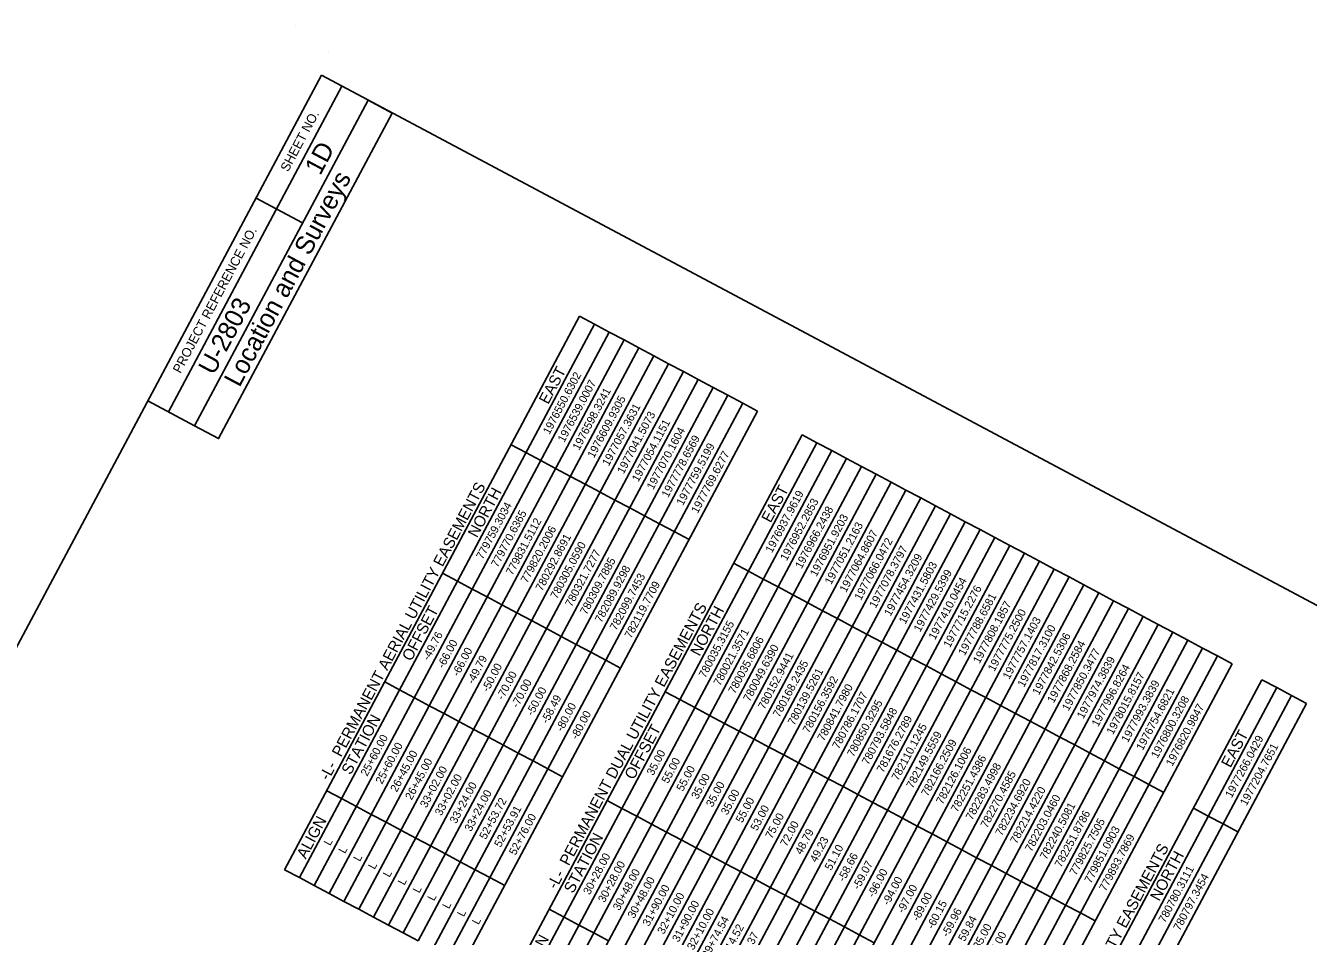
# Model space of a CAD drawing. Extents: x 1979034 to 1987549, y 771535 to 781988.
# Drawn here: x 1981883 to 1985489, y 779426 to 781988 of the extents above; entities that cross this region are included whole.
import ezdxf

# ---------------------------------------------------------------- set-up
doc = ezdxf.new("R2010")
doc.units = 0
for name, color, linetype in [('CTL Sheet Border CELL', 7, 'Continuous'), ('CTL Sheet Notes CELL', 7, 'Continuous'), ('CTL Sheet Table Cell', 7, 'Continuous'), ('CTL Sheet Text', 7, 'Continuous'), ('Old_Level_2', 7, 'Continuous'), ('Sheet Data Field CELL', 7, 'Continuous')]:
    doc.layers.add(name, color=color, linetype=linetype)

msp = doc.modelspace()

# ---------------------------------------------------------------- linework, layer by layer
at = {"layer": 'CTL Sheet Border CELL'}
msp.add_lwpolyline([(1982714.7, 781848.1), (1979034.2, 774941.4), (1983868.8, 772365.1), (1987549.3, 779271.7)], close=True, dxfattribs=at)
at = {"layer": 'CTL Sheet Table Cell'}
for p, q in [((1982611.1, 779613.6), (1983440.7, 781170.4)), ((1982652.8, 779591.4), (1983482.4, 781148.1)), ((1983440.7, 781170.4), (1983482.4, 781148.1)), ((1983482.4, 781148.1), (1983524.1, 781125.9)), ((1982694.5, 779569.2), (1983524.1, 781125.9)), ((1983524.1, 781125.9), (1983565.8, 781103.7)), ((1982736.2, 779546.9), (1983565.8, 781103.7)), ((1982777.9, 779524.7), (1983607.5, 781081.5)), ((1983565.8, 781103.7), (1983607.5, 781081.5)), ((1983607.5, 781081.5), (1983649.2, 781059.3)), ((1982819.6, 779502.5), (1983649.2, 781059.3)), ((1982861.3, 779480.3), (1983690.9, 781037)), ((1983649.2, 781059.3), (1983690.9, 781037)), ((1983690.9, 781037), (1983732.6, 781014.8)), ((1982903, 779458.1), (1983732.6, 781014.8)), ((1983732.6, 781014.8), (1983774.3, 780992.6)), ((1982944.7, 779435.8), (1983774.3, 780992.6)), ((1982986.4, 779413.6), (1983816, 780970.4)), ((1983774.3, 780992.6), (1983816, 780970.4)), ((1983816, 780970.4), (1983857.7, 780948.2)), ((1983028.1, 779391.4), (1983857.7, 780948.2)), ((1983857.7, 780948.2), (1983899.4, 780925.9)), ((1983069.8, 779369.2), (1983899.4, 780925.9)), ((1983111.5, 779347), (1983941.1, 780903.7)), ((1983899.4, 780925.9), (1983941.1, 780903.7)), ((1983236.6, 779280.3), (1984066.2, 780837)), ((1984066.2, 780837), (1984107.9, 780814.8)), ((1983248.2, 780809), (1983289.9, 780786.8)), ((1983278.3, 779258.1), (1984107.9, 780814.8)), ((1983289.9, 780786.8), (1983331.5, 780764.5)), ((1983320, 779235.9), (1984149.6, 780792.6)), ((1984107.9, 780814.8), (1984149.6, 780792.6)), ((1984149.6, 780792.6), (1984191.3, 780770.4)), ((1983331.5, 780764.5), (1983373.2, 780742.3)), ((1983361.7, 779213.6), (1984191.3, 780770.4)), ((1984191.3, 780770.4), (1984233, 780748.2)), ((1983373.2, 780742.3), (1983414.9, 780720.1)), ((1983403.4, 779191.4), (1984233, 780748.2)), ((1983414.9, 780720.1), (1983456.6, 780697.9)), ((1983445.1, 779169.2), (1984274.7, 780725.9)), ((1984233, 780748.2), (1984274.7, 780725.9)), ((1984274.7, 780725.9), (1984316.4, 780703.7)), ((1983456.6, 780697.9), (1983498.3, 780675.6)), ((1983486.8, 779147), (1984316.4, 780703.7)), ((1983528.5, 779124.7), (1984358.1, 780681.5)), ((1984316.4, 780703.7), (1984358.1, 780681.5)), ((1984358.1, 780681.5), (1984399.8, 780659.3)), ((1983498.3, 780675.6), (1983540, 780653.4)), ((1983540, 780653.4), (1983581.7, 780631.2)), ((1983570.2, 779102.5), (1984399.8, 780659.3)), ((1984399.8, 780659.3), (1984441.5, 780637.1)), ((1983581.7, 780631.2), (1983623.4, 780609)), ((1983611.9, 779080.3), (1984441.5, 780637.1)), ((1983623.4, 780609), (1983665.1, 780586.8)), ((1983653.6, 779058.1), (1984483.2, 780614.8)), ((1984441.5, 780637.1), (1984483.2, 780614.8)), ((1984483.2, 780614.8), (1984524.9, 780592.6)), ((1983665.1, 780586.8), (1983706.8, 780564.5)), ((1983695.3, 779035.9), (1984524.9, 780592.6)), ((1983737, 779013.6), (1984566.6, 780570.4)), ((1984524.9, 780592.6), (1984566.6, 780570.4)), ((1984566.6, 780570.4), (1984608.3, 780548.2)), ((1983706.8, 780564.5), (1983748.5, 780542.3)), ((1983778.7, 778991.4), (1984608.3, 780548.2)), ((1984608.3, 780548.2), (1984650, 780526)), ((1983820.4, 778969.2), (1984650, 780526)), ((1983862.1, 778947), (1984691.7, 780503.7)), ((1984650, 780526), (1984691.7, 780503.7)), ((1984691.7, 780503.7), (1984733.4, 780481.5)), ((1983873.6, 780475.7), (1983915.3, 780453.4)), ((1983903.8, 778924.8), (1984733.4, 780481.5)), ((1984733.4, 780481.5), (1984775.1, 780459.3)), ((1983055.6, 780447.6), (1983097.3, 780425.4)), ((1983097.3, 780425.4), (1983139, 780403.1)), ((1983915.3, 780453.4), (1983957, 780431.2)), ((1983945.5, 778902.5), (1984775.1, 780459.3)), ((1983957, 780431.2), (1983998.7, 780409)), ((1983987.2, 778880.3), (1984816.8, 780437.1)), ((1984775.1, 780459.3), (1984816.8, 780437.1)), ((1984816.8, 780437.1), (1984858.5, 780414.8)), ((1983139, 780403.1), (1983180.7, 780380.9)), ((1983998.7, 780409), (1984040.4, 780386.8)), ((1984028.9, 778858.1), (1984858.5, 780414.8)), ((1984070.6, 778835.9), (1984900.2, 780392.6)), ((1984858.5, 780414.8), (1984900.2, 780392.6)), ((1984900.2, 780392.6), (1984941.9, 780370.4)), ((1983180.7, 780380.9), (1983222.4, 780358.7)), ((1983222.4, 780358.7), (1983264.1, 780336.5)), ((1984040.4, 780386.8), (1984082.1, 780364.6)), ((1984082.1, 780364.6), (1984123.8, 780342.3)), ((1984112.3, 778813.7), (1984941.9, 780370.4)), ((1984941.9, 780370.4), (1984983.6, 780348.2)), ((1983264.1, 780336.5), (1983305.8, 780314.3)), ((1984123.8, 780342.3), (1984165.5, 780320.1)), ((1984154, 778791.4), (1984983.6, 780348.2)), ((1984165.5, 780320.1), (1984207.2, 780297.9)), ((1984195.7, 778769.2), (1985025.3, 780326)), ((1984983.6, 780348.2), (1985025.3, 780326)), ((1985025.3, 780326), (1985067, 780303.7)), ((1983305.8, 780314.3), (1983347.5, 780292)), ((1983347.5, 780292), (1983389.2, 780269.8)), ((1984207.2, 780297.9), (1984248.9, 780275.7)), ((1984237.4, 778747), (1985067, 780303.7)), ((1984279.1, 778724.8), (1985108.7, 780281.5)), ((1985067, 780303.7), (1985108.7, 780281.5)), ((1985108.7, 780281.5), (1985150.4, 780259.3)), ((1983389.2, 780269.8), (1983430.9, 780247.6)), ((1983430.9, 780247.6), (1983472.6, 780225.4)), ((1984248.9, 780275.7), (1984290.6, 780253.4)), ((1984290.6, 780253.4), (1984332.3, 780231.2)), ((1984320.8, 778702.5), (1985150.4, 780259.3)), ((1985150.4, 780259.3), (1985192.1, 780237.1)), ((1983472.6, 780225.4), (1983514.3, 780203.2)), ((1984332.3, 780231.2), (1984374, 780209)), ((1984362.5, 778680.3), (1985192.1, 780237.1)), ((1984374, 780209), (1984415.7, 780186.8)), ((1984404.2, 778658.1), (1985233.8, 780214.9)), ((1985192.1, 780237.1), (1985233.8, 780214.9)), ((1985233.8, 780214.9), (1985275.5, 780192.6)), ((1983514.3, 780203.2), (1983556, 780180.9)), ((1984415.7, 780186.8), (1984457.4, 780164.6)), ((1984445.9, 778635.9), (1985275.5, 780192.6)), ((1982892.6, 780141.8), (1982934.3, 780119.6)), ((1984457.4, 780164.6), (1984499.1, 780142.3)), ((1984499.1, 780142.3), (1984540.8, 780120.1)), ((1984529.3, 778591.4), (1985358.9, 780148.2)), ((1985358.9, 780148.2), (1985400.6, 780126)), ((1982934.3, 780119.6), (1982976, 780097.4)), ((1983681.1, 780114.3), (1983722.7, 780092)), ((1984540.8, 780120.1), (1984582.5, 780097.9)), ((1984571, 778569.2), (1985400.6, 780126)), ((1984612.7, 778547), (1985442.3, 780103.8)), ((1985400.6, 780126), (1985442.3, 780103.8)), ((1985442.3, 780103.8), (1985484, 780081.5)), ((1982976, 780097.4), (1983017.7, 780075.1)), ((1983017.7, 780075.1), (1983059.4, 780052.9)), ((1983722.7, 780092), (1983764.4, 780069.8)), ((1983764.4, 780069.8), (1983806.1, 780047.6)), ((1984582.5, 780097.9), (1984624.2, 780075.7)), ((1984624.2, 780075.7), (1984665.9, 780053.5)), ((1984654.4, 778524.8), (1985484, 780081.5)), ((1983059.4, 780052.9), (1983101.1, 780030.7)), ((1983101.1, 780030.7), (1983142.8, 780008.5)), ((1983806.1, 780047.6), (1983847.8, 780025.4)), ((1984665.9, 780053.5), (1984707.6, 780031.2)), ((1984707.6, 780031.2), (1984749.3, 780009)), ((1983142.8, 780008.5), (1983184.5, 779986.2)), ((1983847.8, 780025.4), (1983889.5, 780003.2)), ((1983889.5, 780003.2), (1983931.2, 779980.9)), ((1984749.3, 780009), (1984791, 779986.8)), ((1983184.5, 779986.2), (1983226.2, 779964)), ((1983226.2, 779964), (1983267.9, 779941.8)), ((1983931.2, 779980.9), (1983972.9, 779958.7)), ((1983972.9, 779958.7), (1984014.6, 779936.5)), ((1984791, 779986.8), (1984832.7, 779964.6)), ((1984832.7, 779964.6), (1984874.4, 779942.4)), ((1983267.9, 779941.8), (1983309.6, 779919.6)), ((1983309.6, 779919.6), (1983351.3, 779897.4)), ((1984014.6, 779936.5), (1984056.3, 779914.3)), ((1984874.4, 779942.4), (1984916.1, 779920.1)), ((1984916.1, 779920.1), (1984957.8, 779897.9)), ((1983351.3, 779897.4), (1983393, 779875.1)), ((1984056.3, 779914.3), (1984098, 779892.1)), ((1984098, 779892.1), (1984139.7, 779869.8)), ((1984957.8, 779897.9), (1984999.5, 779875.7)), ((1984139.7, 779869.8), (1984181.4, 779847.6)), ((1984181.4, 779847.6), (1984223.1, 779825.4)), ((1984999.5, 779875.7), (1985041.2, 779853.5)), ((1985041.2, 779853.5), (1985082.9, 779831.2)), ((1982729.7, 779836), (1982771.4, 779813.8)), ((1982771.4, 779813.8), (1982813.1, 779791.6)), ((1984223.1, 779825.4), (1984264.8, 779803.2)), ((1982813.1, 779791.6), (1982854.8, 779769.3)), ((1983518.1, 779808.5), (1983559.8, 779786.3)), ((1983559.8, 779786.3), (1983601.5, 779764)), ((1984264.8, 779803.2), (1984306.5, 779781)), ((1984306.5, 779781), (1984348.2, 779758.7)), ((1985166.3, 779786.8), (1985208, 779764.6)), ((1982854.8, 779769.3), (1982896.5, 779747.1)), ((1982896.5, 779747.1), (1982938.2, 779724.9)), ((1983601.5, 779764), (1983643.2, 779741.8)), ((1983643.2, 779741.8), (1983684.9, 779719.6)), ((1984348.2, 779758.7), (1984389.9, 779736.5)), ((1985208, 779764.6), (1985249.7, 779742.4)), ((1985249.7, 779742.4), (1985291.4, 779720.1)), ((1982938.2, 779724.9), (1982979.9, 779702.7)), ((1983684.9, 779719.6), (1983726.6, 779697.4)), ((1984389.9, 779736.5), (1984431.6, 779714.3)), ((1984431.6, 779714.3), (1984473.3, 779692.1)), ((1982979.9, 779702.7), (1983021.6, 779680.5)), ((1983021.6, 779680.5), (1983063.3, 779658.2)), ((1983726.6, 779697.4), (1983768.3, 779675.2)), ((1983768.3, 779675.2), (1983810, 779652.9)), ((1984473.3, 779692.1), (1984515, 779669.8)), ((1984515, 779669.8), (1984556.7, 779647.6)), ((1983063.3, 779658.2), (1983104.9, 779636)), ((1983104.9, 779636), (1983146.6, 779613.8)), ((1983810, 779652.9), (1983851.7, 779630.7)), ((1983851.7, 779630.7), (1983893.4, 779608.5)), ((1984556.7, 779647.6), (1984598.4, 779625.4)), ((1982611.1, 779613.6), (1982652.8, 779591.4)), ((1983146.6, 779613.8), (1983188.3, 779591.6)), ((1983893.4, 779608.5), (1983935.1, 779586.3)), ((1984598.4, 779625.4), (1984640.1, 779603.2)), ((1984640.1, 779603.2), (1984681.8, 779581)), ((1982652.8, 779591.4), (1982694.5, 779569.2)), ((1982694.5, 779569.2), (1982736.2, 779546.9)), ((1983188.3, 779591.6), (1983230, 779569.4)), ((1983935.1, 779586.3), (1983976.8, 779564)), ((1983976.8, 779564), (1984018.5, 779541.8)), ((1984681.8, 779581), (1984723.5, 779558.7)), ((1984723.5, 779558.7), (1984765.2, 779536.5)), ((1982736.2, 779546.9), (1982777.9, 779524.7)), ((1982777.9, 779524.7), (1982819.6, 779502.5)), ((1984018.5, 779541.8), (1984060.2, 779519.6)), ((1984765.2, 779536.5), (1984806.9, 779514.3)), ((1982819.6, 779502.5), (1982861.3, 779480.3)), ((1983355.1, 779502.7), (1983396.8, 779480.5)), ((1984060.2, 779519.6), (1984101.9, 779497.4)), ((1984101.9, 779497.4), (1984143.6, 779475.2)), ((1984806.9, 779514.3), (1984848.6, 779492.1)), ((1984848.6, 779492.1), (1984890.3, 779469.9)), ((1982861.3, 779480.3), (1982903, 779458.1)), ((1982903, 779458.1), (1982944.7, 779435.8)), ((1983396.8, 779480.5), (1983438.5, 779458.2)), ((1983438.5, 779458.2), (1983480.2, 779436)), ((1984143.6, 779475.2), (1984185.3, 779452.9)), ((1984185.3, 779452.9), (1984227, 779430.7)), ((1982944.7, 779435.8), (1982986.4, 779413.6)), ((1983480.2, 779436), (1983521.9, 779413.8)), ((1984227, 779430.7), (1984268.7, 779408.5))]:
    msp.add_line(p, q, dxfattribs=at)
at = {"layer": 'Sheet Data Field CELL'}
for p, q in [((1982641.3, 781987.7), (1982641.3, 781987.7)), ((1982733.6, 781911.9), (1982733.6, 781911.9)), ((1982733.6, 781911.9), (1982733.6, 781911.9)), ((1982284.4, 780901.4), (1982772.5, 781817.3)), ((1982530.9, 781502.6), (1982661.9, 781432.8)), ((1982226.8, 780932), (1982357.9, 780862.2))]:
    msp.add_line(p, q, dxfattribs=at)
msp.add_lwpolyline([(1982357.9, 780862.2), (1982845.9, 781778.1), (1982913.7, 781742), (1982425.6, 780826.1)], close=True, dxfattribs=at)

# ---------------------------------------------------------------- texts
at = {"layer": 'CTL Sheet Notes CELL'}
for s, p in [('EAST', (1983352.2, 780920.6)), ('-L-  PERMANENT AERIAL UTILITY EASEMENTS', (1982734.8, 779862.5)), ('NORTH', (1983152.3, 780545.4)), ('EAST', (1983977.7, 780587.3)), ('OFFSET', (1982967.2, 780198)), ('-L-  PERMANENT DUAL UTILITY EASEMENTS', (1983375, 779556.7)), ('NORTH', (1983777.8, 780212.1)), ('STATION', (1982796.9, 779878.4)), ('OFFSET', (1983592.7, 779864.7)), ('EAST', (1985270.4, 779898.4)), ('ALIGN', (1982670.9, 779641.9)), ('STATION', (1983422.4, 779545.1)), ('-Y5-  PERMANENT DUAL UTILITY EASEMENTS', (1984660.3, 778854.1)), ('NORTH', (1985070.5, 779523.2)), ('ALIGN', (1983296.3, 779308.6))]:
    msp.add_text(s, height=31.5, rotation=61.9471, dxfattribs=at).set_placement(p)
at = {"layer": 'CTL Sheet Text'}
for s, p in [('1976550.6302', (1983355.7, 780836.1)), ('1976539.0007', (1983397.4, 780813.9)), ('1976598.3241', (1983439.1, 780791.7)), ('1976609.9305', (1983480.8, 780769.5)), ('1977057.3631', (1983522.5, 780747.2)), ('1977041.5073', (1983564.2, 780725)), ('1977054.1151', (1983605.9, 780702.8)), ('1977070.1604', (1983647.6, 780680.6)), ('1977778.6569', (1983689.3, 780658.4)), ('1977759.5199', (1983731, 780636.1)), ('1977769.6277', (1983772.7, 780613.9)), ('1976937.9619', (1983981.2, 780502.8)), ('779759.3034', (1983168.3, 780484.6)), ('1976952.2853', (1984022.9, 780480.6)), ('779770.6365', (1983210, 780462.4)), ('1976966.2438', (1984064.6, 780458.4)), ('1976951.9203', (1984106.3, 780436.2)), ('779831.5112', (1983251.7, 780440.1)), ('779820.2006', (1983293.4, 780417.9)), ('1977051.2163', (1984148, 780413.9)), ('1977064.8607', (1984189.7, 780391.7)), ('780292.8691', (1983335.1, 780395.7)), ('780305.0590', (1983376.8, 780373.5)), ('1977066.0472', (1984231.4, 780369.5)), ('780321.7277', (1983418.5, 780351.3)), ('1977078.3797', (1984273.1, 780347.3)), ('1977454.3209', (1984314.8, 780325)), ('780309.7885', (1983460.2, 780329)), ('782089.9298', (1983501.9, 780306.8)), ('1977431.5803', (1984356.5, 780302.8)), ('782099.7453', (1983543.6, 780284.6)), ('782119.7709', (1983585.3, 780262.4)), ('1977429.5399', (1984398.1, 780280.6)), ('1977410.0454', (1984439.8, 780258.4)), ('1977715.2276', (1984481.5, 780236.2)), ('1977788.6581', (1984523.2, 780213.9)), ('1977808.1857', (1984564.9, 780191.7)), ('1977775.2500', (1984606.6, 780169.5)), ('1977757.1403', (1984648.3, 780147.3)), ('-49.76', (1983016.8, 780200.3)), ('780035.3155', (1983793.8, 780151.3)), ('780021.3571', (1983835.5, 780129.1)), ('1977817.3100', (1984690, 780125.1)), ('1977842.5306', (1984731.7, 780102.8)), ('-66.00', (1983058.5, 780178)), ('780035.6806', (1983877.2, 780106.8)), ('780049.6390', (1983918.9, 780084.6)), ('1977868.2584', (1984773.4, 780080.6)), ('-66.00', (1983100.2, 780155.8)), ('-49.79', (1983141.9, 780133.6)), ('780152.9441', (1983960.6, 780062.4)), ('1977850.3477', (1984815.1, 780058.4)), ('1977974.3839', (1984856.8, 780036.2)), ('-50.00', (1983183.6, 780111.4)), ('780168.2435', (1984002.3, 780040.2)), ('780139.5261', (1984044, 780017.9)), ('1977996.8264', (1984898.5, 780014)), ('-70.00', (1983225.3, 780089.1)), ('-70.00', (1983267, 780066.9)), ('780156.3592', (1984085.7, 779995.7)), ('780841.7980', (1984127.4, 779973.5)), ('1978015.8157', (1984940.2, 779991.7)), ('1977993.3839', (1984981.9, 779969.5)), ('-50.00', (1983308.7, 780044.7)), ('-58.49', (1983350.4, 780022.5)), ('780786.1707', (1984169.1, 779951.3)), ('1976754.6821', (1985023.6, 779947.3)), ('1976800.3208', (1985065.3, 779925.1)), ('-80.00', (1983392.1, 780000.3)), ('780850.3295', (1984210.8, 779929.1)), ('780793.5848', (1984252.5, 779906.8)), ('1976820.9847', (1985107, 779902.8)), ('-80.00', (1983433.8, 779978)), ('781676.2789', (1984294.2, 779884.6)), ('25+60.00', (1982843.4, 779874.8)), ('782110.1245', (1984335.9, 779862.4)), ('782149.5559', (1984377.6, 779840.2)), ('25+60.00', (1982885.1, 779852.5)), ('782166.2509', (1984419.3, 779818)), ('782126.1006', (1984461, 779795.7)), ('1977266.0429', (1985273.8, 779814)), ('1977204.7651', (1985315.5, 779791.7)), ('26+45.00', (1982926.8, 779830.3)), ('26+45.00', (1982968.5, 779808.1)), ('35.00', (1983647.6, 779876.8)), ('55.00', (1983689.3, 779854.6)), ('782251.4386', (1984502.7, 779773.5)), ('33+02.00', (1983010.2, 779785.9)), ('55.00', (1983731, 779832.3)), ('35.00', (1983772.7, 779810.1)), ('782283.4998', (1984544.4, 779751.3)), ('782270.4585', (1984586.1, 779729.1)), ('33+02.00', (1983051.9, 779763.7)), ('33+24.00', (1983093.6, 779741.4)), ('35.00', (1983814.3, 779787.9)), ('782234.6920', (1984627.8, 779706.9)), ('33+24.00', (1983135.3, 779719.2)), ('52+53.72', (1983177, 779697)), ('35.00', (1983856, 779765.7)), ('55.00', (1983897.7, 779743.5)), ('782214.4220', (1984669.5, 779684.6)), ('782203.0460', (1984711.2, 779662.4)), ('52+53.91', (1983218.7, 779674.8)), ('53.00', (1983939.4, 779721.2)), ('782240.5081', (1984752.9, 779640.2)), ('782251.8786', (1984794.6, 779618)), ('52+76.00', (1983260.4, 779652.5)), ('75.00', (1983981.1, 779699)), ('72.00', (1984022.8, 779676.8)), ('779825.7505', (1984836.3, 779595.7)), ('48.79', (1984064.5, 779654.6)), ('49.23', (1984106.2, 779632.4)), ('779851.0903', (1984878, 779573.5)), ('779893.7869', (1984919.7, 779551.3)), ('L', (1982739.4, 779679.6)), ('L', (1982781.1, 779657.4)), ('51.10', (1984147.9, 779610.1)), ('L', (1982822.8, 779635.2)), ('30+28.00', (1983468.9, 779541.4)), ('30+28.00', (1983510.6, 779519.2)), ('-58.66', (1984184.4, 779578.1)), ('-59.07', (1984226.1, 779555.8)), ('L', (1982864.5, 779613)), ('L', (1982906.2, 779590.7)), ('30+48.00', (1983552.3, 779497)), ('-96.00', (1984267.8, 779533.6)), ('780780.3111', (1985086.5, 779462.4)), ('780797.3454', (1985128.2, 779440.2)), ('L', (1982947.9, 779568.5)), ('L', (1982989.6, 779546.3)), ('30+48.00', (1983593.9, 779474.8)), ('31+90.00', (1983635.6, 779452.6)), ('-94.00', (1984309.5, 779511.4)), ('-97.00', (1984351.2, 779489.2)), ('L', (1983031.3, 779524.1)), ('32+10.00', (1983677.3, 779430.3)), ('31+90.00', (1983719, 779408.1)), ('-89.00', (1984392.9, 779467)), ('-60.15', (1984434.6, 779444.7)), ('L', (1983073, 779501.9)), ('L', (1983114.7, 779479.6)), ('32+10.00', (1983760.7, 779385.9)), ('-59.96', (1984476.3, 779422.5)), ('L', (1983156.4, 779457.4)), ('39+74.54', (1983802.4, 779363.7)), ('39+14.52', (1983844.1, 779341.5)), ('59.84', (1984523.2, 779410.1)), ('85.00', (1984564.9, 779387.9)), ('39+74.37', (1983885.8, 779319.2)), ('85.00', (1984606.6, 779365.7))]:
    msp.add_text(s, height=22.5, rotation=61.9471, dxfattribs=at).set_placement(p)
at = {"layer": 'Old_Level_2'}
for s, height, p in [('THE LOCALIZED COORDINATE SYSTEM DEVELOPED FOR THIS PROJECT', 40.6, (1985441, 778236.1)), ('DATUM DESCRIPTION', 72.178, (1985500.9, 778570.8))]:
    msp.add_text(s, height=height, rotation=61.9471, dxfattribs=at).set_placement(p)
at = {"layer": 'Sheet Data Field CELL'}
for s, height, p in [('SHEET NO.', 26.09, (1982621, 781574.7)), ('1D', 52.17, (1982711.4, 781564.2)), ('Location and Surveys', 52.175, (1982484.4, 780968.3)), ('PROJECT REFERENCE NO.', 26.087, (1982318.4, 781007.9)), ('U-2803', 52.17, (1982412, 781002.3))]:
    msp.add_text(s, height=height, rotation=61.9471, dxfattribs=at).set_placement(p)

doc.saveas('drawing.dxf')
